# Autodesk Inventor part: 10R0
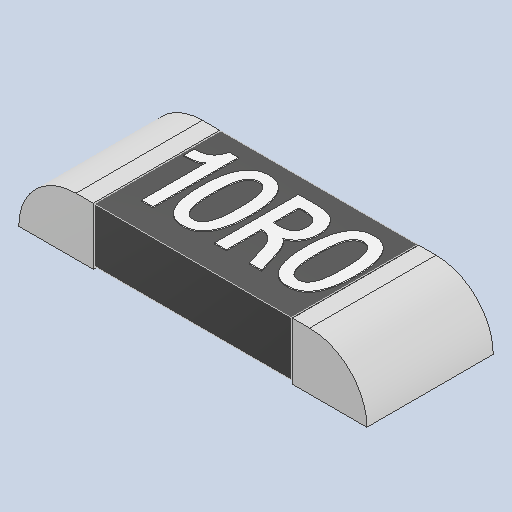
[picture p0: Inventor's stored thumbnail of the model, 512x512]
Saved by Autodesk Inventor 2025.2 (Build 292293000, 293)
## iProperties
Created: 2025-04
Part Number: 10R0
Material: Generic
Description: PART--DESC
Document SubType Name: Modeling
Designer: BennF
Density: 1 g/cm^3
Appearance: Default
Author: BennF
Revision Number: NONE
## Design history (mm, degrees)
feature "pin"
feature "Solid"
feature "1"
feature "0"
feature "R"
feature "0:1"
body "Solid1"
body "Solid2"
body "Solid3"
body "Solid4"
body "Solid5"
body "Solid6"
